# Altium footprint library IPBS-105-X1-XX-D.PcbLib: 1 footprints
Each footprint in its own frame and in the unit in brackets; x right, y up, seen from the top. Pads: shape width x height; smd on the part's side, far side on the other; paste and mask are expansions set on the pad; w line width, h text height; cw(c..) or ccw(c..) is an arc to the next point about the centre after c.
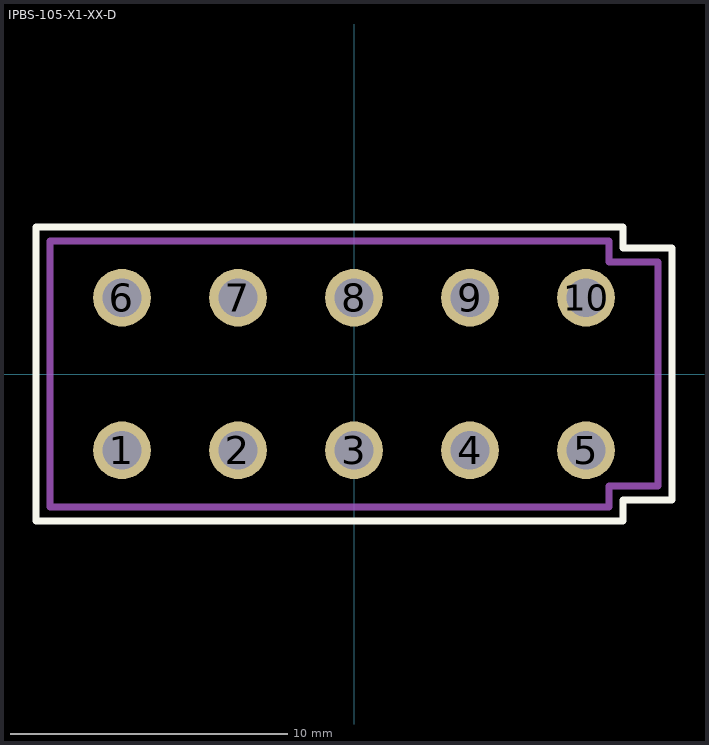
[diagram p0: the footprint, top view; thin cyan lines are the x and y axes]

## IPBS-105-X1-XX-D [mil]
pads (10):
  round 82 hole 55 mask+3: 1(-330,-108.5) 2(-165,-108.5) 3(0,-108.5) 4(165,-108.5) 5(330,-108.5) 6(-330,108.5) 7(-165,108.5) 8(0,108.5) 9(165,108.5) 10(330,108.5)
Top Overlay:
  lines w10: -452.5,-209 -452.5,209 382.5,209 382.5,179 452.5,179 452.5,-179 382.5,-179 382.5,-209 -452.5,-209
Mechanical 1:
  lines w10: -432.5,-189 -432.5,189 362.5,189 362.5,159 432.5,159 432.5,-159 362.5,-159 362.5,-189 -432.5,-189
  text "J1" at -23.42,-24 h40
